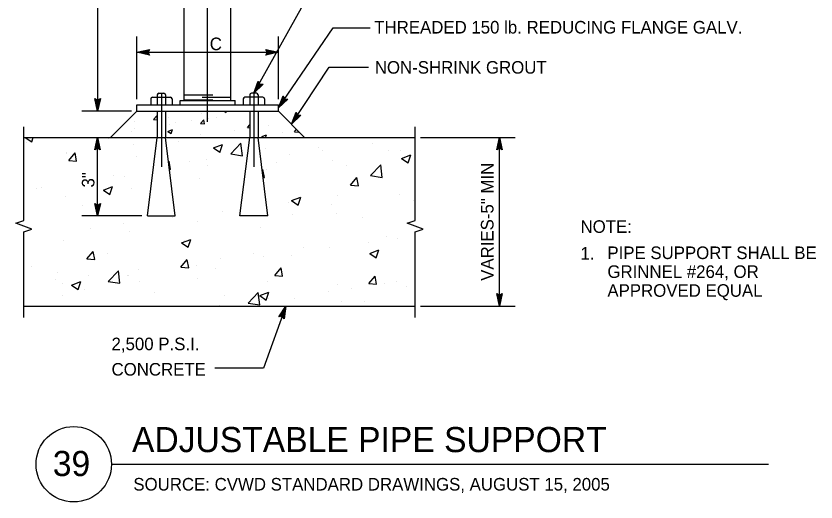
# Model space of a CAD drawing. Extents: x -121875 to -117742, y -103854 to -101122.
# Drawn here: x -121098.1 to -120716.3, y -102136.5 to -101904.5 of the extents above; entities that cross this region are included whole.
import ezdxf

# ---------------------------------------------------------------- set-up
doc = ezdxf.new("R2010")
doc.units = 0
for name, color, linetype in [('G-MARK', 7, 'Continuous'), ('G-TEXT', 7, 'Continuous'), ('Misc CnstDet(22)', 7, 'Continuous')]:
    doc.layers.add(name, color=color, linetype=linetype)

msp = doc.modelspace()

# ---------------------------------------------------------------- linework, layer by layer
at = {"layer": 'G-MARK'}
for p, q in [((-121059.15, -101866.71), (-121059.15, -101949.94)), ((-121040.4, -101944.19), (-121040.4, -101914.32)), ((-120972.82, -101944.19), (-120972.82, -101914.32)), ((-121040.4, -101921.82), (-120972.82, -101921.82)), ((-121043.02, -101949.94), (-121066.65, -101949.94)), ((-121059.15, -101999.94), (-121059.15, -101962.44)), ((-120904.96, -101962.44), (-120859.85, -101962.44)), ((-120867.35, -102042.91), (-120867.35, -101962.44)), ((-121037.94, -101999.94), (-121066.65, -101999.94)), ((-120904.96, -102042.91), (-120859.85, -102042.91))]:
    msp.add_line(p, q, dxfattribs=at)
for points in [[(-120984.54, -101941.35), (-120937.41, -101856.81), (-120928.5, -101856.81)], [(-120972.82, -101948.38), (-120946.65, -101910.1), (-120929.07, -101910.1)], [(-120966.57, -101956.19), (-120948.6, -101928.85), (-120929.85, -101928.85)], [(-120969.3, -102042.91), (-120980.01, -102072.63), (-121003.19, -102072.65)]]:
    msp.add_lwpolyline(points, dxfattribs=at)
at = {"layer": 'G-TEXT'}
for p, q in [((-121040.4, -101921.82), (-121034.4, -101920.49)), ((-121034.4, -101923.16), (-121040.4, -101921.82)), ((-121040.4, -101921.82), (-121040.4, -101921.82)), ((-121034.61, -101922.8), (-121039.02, -101921.82)), ((-121039, -101921.82), (-121034.63, -101920.85)), ((-121037.63, -101921.82), (-121034.81, -101921.19)), ((-121034.85, -101922.44), (-121037.63, -101921.82)), ((-121036.25, -101921.82), (-121035.04, -101921.55)), ((-121035.02, -101922.1), (-121036.25, -101921.82)), ((-121034.4, -101920.49), (-121035.2, -101921.82)), ((-121035.2, -101921.82), (-121034.4, -101923.16)), ((-121034.4, -101920.49), (-121034.4, -101920.49)), ((-120978.02, -101921.82), (-120978.82, -101920.48)), ((-120978.82, -101920.48), (-120978.82, -101920.48)), ((-120978.82, -101920.48), (-120972.82, -101921.82)), ((-120972.82, -101921.82), (-120978.82, -101923.15)), ((-120978.82, -101923.15), (-120978.02, -101921.82)), ((-120978.6, -101920.83), (-120974.2, -101921.82)), ((-120974.21, -101921.82), (-120978.58, -101922.79)), ((-120975.58, -101921.82), (-120978.41, -101922.44)), ((-120978.37, -101921.19), (-120975.58, -101921.82)), ((-120978.19, -101921.54), (-120976.96, -101921.82)), ((-120976.96, -101921.82), (-120978.17, -101922.08)), ((-120972.82, -101921.82), (-120972.82, -101921.82)), ((-121034.4, -101923.16), (-121034.4, -101923.16)), ((-120978.82, -101923.15), (-120978.82, -101923.15)), ((-120984.54, -101941.35), (-120982.44, -101935.57)), ((-120980.19, -101937.01), (-120984.54, -101941.35)), ((-120980.6, -101937), (-120983.8, -101940.19)), ((-120983.79, -101940.17), (-120982.26, -101935.96)), ((-120983.05, -101939.02), (-120982.06, -101936.3)), ((-120981.03, -101937), (-120983.05, -101939.02)), ((-120982.44, -101935.57), (-120982.44, -101935.57)), ((-120982.44, -101935.57), (-120981.75, -101936.96)), ((-120982.31, -101937.85), (-120981.89, -101936.69)), ((-120981.42, -101936.96), (-120982.31, -101937.85)), ((-120981.75, -101936.96), (-120980.19, -101937.01)), ((-120980.19, -101937.01), (-120980.19, -101937.01)), ((-120984.54, -101941.35), (-120984.54, -101941.35)), ((-121059.15, -101949.94), (-121060.48, -101943.94)), ((-121060.48, -101943.94), (-121060.48, -101943.94)), ((-121060.48, -101943.94), (-121059.15, -101944.74)), ((-121059.15, -101948.55), (-121060.12, -101944.18)), ((-121059.14, -101947.18), (-121059.77, -101944.36)), ((-121059.14, -101945.8), (-121059.41, -101944.59)), ((-121059.15, -101944.74), (-121057.81, -101943.94)), ((-121057.81, -101943.94), (-121059.15, -101949.94)), ((-121058.16, -101944.16), (-121059.15, -101948.56)), ((-121058.52, -101944.39), (-121059.14, -101947.18)), ((-121058.87, -101944.57), (-121059.14, -101945.8)), ((-121057.81, -101943.94), (-121057.81, -101943.94)), ((-120972.82, -101948.38), (-120970.53, -101942.68)), ((-120968.33, -101944.18), (-120972.82, -101948.38)), ((-120972.04, -101947.23), (-120970.37, -101943.07)), ((-120968.74, -101944.16), (-120972.04, -101947.24)), ((-120971.26, -101946.1), (-120970.18, -101943.42)), ((-120969.17, -101944.15), (-120971.26, -101946.1)), ((-120970.53, -101942.68), (-120970.53, -101942.68)), ((-120970.53, -101942.68), (-120969.88, -101944.09)), ((-120970.48, -101944.96), (-120970.02, -101943.81)), ((-120969.56, -101944.1), (-120970.48, -101944.96)), ((-120969.88, -101944.09), (-120968.33, -101944.18)), ((-120968.33, -101944.18), (-120968.33, -101944.18)), ((-120972.82, -101948.38), (-120972.82, -101948.38)), ((-121059.15, -101949.94), (-121059.15, -101949.94)), ((-120966.57, -101956.19), (-120964.41, -101950.44)), ((-120962.17, -101951.9), (-120966.57, -101956.19)), ((-120965.81, -101955.03), (-120964.24, -101950.83)), ((-120962.59, -101951.88), (-120965.81, -101955.04)), ((-120965.06, -101953.88), (-120964.04, -101951.17)), ((-120963.02, -101951.88), (-120965.06, -101953.88)), ((-120964.41, -101950.44), (-120964.41, -101950.44)), ((-120964.41, -101950.44), (-120963.73, -101951.84)), ((-120964.3, -101952.72), (-120963.87, -101951.56)), ((-120963.4, -101951.84), (-120964.3, -101952.72)), ((-120963.73, -101951.84), (-120962.17, -101951.9)), ((-120962.17, -101951.9), (-120962.17, -101951.9)), ((-120966.57, -101956.19), (-120966.57, -101956.19)), ((-121060.49, -101968.44), (-121059.15, -101962.44)), ((-121060.13, -101968.23), (-121059.15, -101963.82)), ((-121059.15, -101962.44), (-121059.15, -101962.44)), ((-121059.15, -101962.44), (-121057.82, -101968.44)), ((-121059.14, -101963.83), (-121058.17, -101968.21)), ((-120868.69, -101968.44), (-120867.35, -101962.44)), ((-120868.33, -101968.23), (-120867.35, -101963.82)), ((-120867.35, -101962.44), (-120867.35, -101962.44)), ((-120867.35, -101962.44), (-120866.02, -101968.44)), ((-120867.35, -101963.83), (-120866.38, -101968.21)), ((-121059.15, -101967.64), (-121060.49, -101968.44)), ((-121059.77, -101967.99), (-121059.15, -101965.21)), ((-121059.42, -101967.82), (-121059.15, -101966.59)), ((-121059.15, -101965.21), (-121058.52, -101968.03)), ((-121059.15, -101966.59), (-121058.88, -101967.8)), ((-121057.82, -101968.44), (-121059.15, -101967.64)), ((-120867.35, -101967.64), (-120868.69, -101968.44)), ((-120867.97, -101967.99), (-120867.35, -101965.21)), ((-120867.63, -101967.82), (-120867.35, -101966.59)), ((-120867.35, -101965.21), (-120866.72, -101968.03)), ((-120867.35, -101966.59), (-120867.08, -101967.8)), ((-120866.02, -101968.44), (-120867.35, -101967.64)), ((-121060.49, -101968.44), (-121060.49, -101968.44)), ((-121057.82, -101968.44), (-121057.82, -101968.44)), ((-120868.69, -101968.44), (-120868.69, -101968.44)), ((-120866.02, -101968.44), (-120866.02, -101968.44)), ((-121059.15, -101999.94), (-121060.48, -101993.94)), ((-121060.48, -101993.94), (-121060.48, -101993.94)), ((-121060.48, -101993.94), (-121059.15, -101994.74)), ((-121059.15, -101998.55), (-121060.12, -101994.18)), ((-121059.14, -101997.18), (-121059.77, -101994.36)), ((-121059.14, -101995.8), (-121059.41, -101994.59)), ((-121059.15, -101994.74), (-121057.81, -101993.94)), ((-121057.81, -101993.94), (-121059.15, -101999.94)), ((-121058.16, -101994.16), (-121059.15, -101998.56)), ((-121058.52, -101994.39), (-121059.14, -101997.18)), ((-121058.87, -101994.57), (-121059.14, -101995.8)), ((-121057.81, -101993.94), (-121057.81, -101993.94)), ((-121059.15, -101999.94), (-121059.15, -101999.94)), ((-120867.35, -102042.91), (-120868.68, -102036.91)), ((-120868.68, -102036.91), (-120868.68, -102036.91)), ((-120868.68, -102036.91), (-120867.35, -102037.71)), ((-120867.35, -102041.52), (-120868.32, -102037.15)), ((-120867.35, -102040.15), (-120867.97, -102037.32)), ((-120867.35, -102038.77), (-120867.61, -102037.56)), ((-120867.35, -102037.71), (-120866.01, -102036.91)), ((-120866.01, -102036.91), (-120867.35, -102042.91)), ((-120866.36, -102037.13), (-120867.35, -102041.53)), ((-120866.72, -102037.36), (-120867.35, -102040.15)), ((-120867.07, -102037.54), (-120867.35, -102038.77)), ((-120866.01, -102036.91), (-120866.01, -102036.91)), ((-120972.59, -102048.11), (-120969.3, -102042.91)), ((-120972.18, -102048.02), (-120969.77, -102044.21)), ((-120969.77, -102044.22), (-120970.34, -102048.67)), ((-120969.3, -102042.91), (-120970.08, -102049.01)), ((-120969.3, -102042.91), (-120969.3, -102042.91)), ((-120867.35, -102042.91), (-120867.35, -102042.91)), ((-120971.06, -102047.81), (-120972.59, -102048.11)), ((-120972.59, -102048.11), (-120972.59, -102048.11)), ((-120971.76, -102047.93), (-120970.24, -102045.51)), ((-120971.38, -102047.88), (-120970.7, -102046.81)), ((-120970.08, -102049.01), (-120971.06, -102047.81)), ((-120970.7, -102046.81), (-120970.86, -102048.04)), ((-120970.24, -102045.51), (-120970.6, -102048.38)), ((-120970.08, -102049.01), (-120970.08, -102049.01))]:
    msp.add_line(p, q, dxfattribs=at)
at = {"layer": 'Misc CnstDet(22)'}
for p, q in [((-121006.61, -101955.02), (-121006.61, -101695.26)), ((-121017.74, -101944.87), (-121017.74, -101832.76)), ((-120995.47, -101944.87), (-120995.47, -101832.76)), ((-121029.85, -101941.35), (-121027.51, -101941.35)), ((-121028.68, -101941.35), (-121028.68, -101976.51)), ((-120983.36, -101941.35), (-120985.71, -101941.35)), ((-120984.54, -101941.35), (-120984.54, -101976.51)), ((-121033.76, -101944.08), (-121033.76, -101946.82)), ((-121032.97, -101943.3), (-121024.38, -101943.3)), ((-121030.63, -101942.13), (-121030.63, -101946.82)), ((-121026.72, -101942.13), (-121026.72, -101946.82)), ((-121023.6, -101944.08), (-121023.6, -101946.82)), ((-121019.69, -101944.87), (-120993.52, -101944.87)), ((-121019.69, -101946.82), (-121019.69, -101944.87)), ((-121017.74, -101942.13), (-121004.07, -101942.13)), ((-121017.74, -101944.48), (-121004.07, -101944.48)), ((-121009.15, -101943.3), (-120995.47, -101943.3)), ((-120993.52, -101946.82), (-120993.52, -101944.87)), ((-120989.61, -101944.08), (-120989.61, -101946.82)), ((-120980.24, -101943.3), (-120988.83, -101943.3)), ((-120986.49, -101942.13), (-120986.49, -101946.82)), ((-120982.58, -101942.13), (-120982.58, -101946.82)), ((-120979.46, -101944.08), (-120979.46, -101946.82)), ((-121040.4, -101946.82), (-120972.82, -101946.82)), ((-121040.4, -101949.94), (-121040.4, -101946.82)), ((-120972.82, -101949.94), (-120972.82, -101946.82)), ((-121052.9, -101962.44), (-121040.4, -101949.94)), ((-121040.4, -101949.94), (-120972.82, -101949.94)), ((-121032.38, -101953.86), (-121030.88, -101952.07)), ((-121030.63, -101953.41), (-121030.88, -101952.07)), ((-121030.63, -101949.94), (-121030.63, -101962.44)), ((-121026.72, -101949.94), (-121026.72, -101962.44)), ((-121009.54, -101950.87), (-121009.54, -101950.87)), ((-120998.7, -101949.94), (-120997.82, -101950.54)), ((-120997.82, -101950.55), (-120997.61, -101949.94)), ((-120988.14, -101950.12), (-120988.14, -101950.12)), ((-120986.49, -101949.94), (-120986.49, -101962.44)), ((-120982.58, -101949.94), (-120982.58, -101962.44)), ((-120982.53, -101950.26), (-120982.53, -101950.26)), ((-120960.32, -101962.44), (-120972.82, -101949.94)), ((-121041.37, -101955.07), (-121041.37, -101955.07)), ((-121032.38, -101953.86), (-121030.63, -101954.02)), ((-121025.33, -101952.87), (-121025.33, -101952.87)), ((-121024.59, -101956.37), (-121024.59, -101956.37)), ((-121021.92, -101955.44), (-121021.92, -101955.44)), ((-121014.1, -101954.41), (-121014.1, -101954.41)), ((-121009.97, -101955.82), (-121008.46, -101954.03)), ((-121009.97, -101955.82), (-121008.1, -101955.99)), ((-121008.1, -101955.99), (-121008.46, -101954.03)), ((-121006.36, -101953.25), (-121006.36, -101953.25)), ((-121002.26, -101952.86), (-121002.26, -101952.86)), ((-120987.56, -101957.78), (-120986.49, -101956.51)), ((-121042.81, -101959.5), (-121042.81, -101959.5)), ((-121041.66, -101958.04), (-121041.66, -101958.04)), ((-121025.63, -101959.57), (-121023.44, -101958.73)), ((-121025.63, -101959.57), (-121024.07, -101960.62)), ((-121024.07, -101960.63), (-121023.44, -101958.74)), ((-120993.69, -101958.93), (-120993.69, -101958.93)), ((-120987.56, -101957.78), (-120986.49, -101957.88)), ((-120977.65, -101956.73), (-120977.65, -101956.73)), ((-120971.09, -101960), (-120971.09, -101960)), ((-120965.14, -101959.74), (-120964.17, -101958.59)), ((-120965.14, -101959.74), (-120963.27, -101959.91)), ((-120963.27, -101959.92), (-120963.37, -101959.39)), ((-121094.3, -101962.44), (-120907.58, -101962.44)), ((-121093.67, -101962.46), (-121093.63, -101962.44)), ((-121093.67, -101962.46), (-121090.56, -101964.56)), ((-121090.56, -101964.57), (-121089.85, -101962.44)), ((-121053.73, -101963.06), (-121053.73, -101963.06)), ((-121035.32, -101999.94), (-121030.63, -101962.44)), ((-121022.04, -101999.94), (-121026.72, -101962.44)), ((-121009.92, -101961.27), (-121009.92, -101961.27)), ((-120991.18, -101999.94), (-120986.49, -101962.44)), ((-120977.9, -101999.94), (-120982.58, -101962.44)), ((-120980.72, -101962.08), (-120978.53, -101961.24)), ((-120980.72, -101962.08), (-120980.17, -101962.44)), ((-120978.93, -101962.44), (-120978.53, -101961.24)), ((-121092.89, -101964.79), (-121092.89, -101964.79)), ((-121042.2, -101965.81), (-121042.2, -101965.81)), ((-121020.37, -101964.47), (-121020.37, -101964.47)), ((-121003.85, -101967.47), (-120999.47, -101965.79)), ((-121003.85, -101967.47), (-121000.74, -101969.56)), ((-121000.74, -101969.57), (-120999.47, -101965.79)), ((-120995.58, -101970.3), (-120990.71, -101965.23)), ((-120990.02, -101971.17), (-120990.71, -101965.24)), ((-120987, -101965.88), (-120987, -101965.88)), ((-120978.81, -101967.92), (-120978.81, -101967.92)), ((-120953.64, -101967.29), (-120953.64, -101967.29)), ((-120928.08, -101965.58), (-120928.08, -101965.58)), ((-121073.92, -101970.05), (-121073.92, -101970.05)), ((-121073.77, -101969.81), (-121073.77, -101969.81)), ((-121072.88, -101973.45), (-121069.86, -101969.85)), ((-121069.14, -101973.78), (-121069.86, -101969.86)), ((-121059.15, -101977.44), (-121059.15, -101969.94)), ((-121040.55, -101971.46), (-121040.55, -101971.46)), ((-120995.58, -101970.3), (-120990.02, -101971.17)), ((-120967.4, -101970.75), (-120967.4, -101970.75)), ((-120951.75, -101968.69), (-120951.75, -101968.69)), ((-120920.27, -101968.7), (-120920.27, -101968.7)), ((-120914.38, -101968.85), (-120914.38, -101968.85)), ((-120914.03, -101972.47), (-120909.65, -101970.79)), ((-120910.92, -101974.58), (-120909.65, -101970.8)), ((-121072.88, -101973.45), (-121069.14, -101973.77)), ((-121025.27, -101974.06), (-121025.04, -101973.78)), ((-121024.31, -101977.7), (-121025.03, -101973.78)), ((-121015.26, -101974.17), (-121015.26, -101974.17)), ((-121007.19, -101972.87), (-121007.19, -101972.87)), ((-120973.82, -101974.28), (-120973.82, -101974.28)), ((-120946.84, -101973.53), (-120946.84, -101973.53)), ((-120940.46, -101975.69), (-120940.46, -101975.69)), ((-120928.88, -101980.65), (-120924.01, -101975.57)), ((-120923.32, -101981.52), (-120924.01, -101975.58)), ((-120914.03, -101972.47), (-120910.92, -101974.57)), ((-121024.82, -101977.65), (-121024.31, -101977.69)), ((-121006.87, -101975.95), (-121006.87, -101975.95)), ((-120980.62, -101978.19), (-120980.21, -101977.7)), ((-120979.48, -101981.62), (-120980.21, -101977.71)), ((-120978.41, -101977.53), (-120978.41, -101977.53)), ((-121051.71, -101980.43), (-121051.71, -101980.43)), ((-121046.19, -101981.13), (-121046.19, -101981.13)), ((-121010.5, -101981.93), (-121010.5, -101981.93)), ((-120980.19, -101981.55), (-120979.48, -101981.62)), ((-120938.39, -101985.21), (-120935.38, -101981.62)), ((-120934.65, -101985.55), (-120935.38, -101981.63)), ((-120928.88, -101980.65), (-120923.32, -101981.51)), ((-121088.16, -101986.69), (-121088.16, -101986.69)), ((-121085.66, -101986.32), (-121085.66, -101986.32)), ((-121056.36, -101987.63), (-121051.99, -101985.95)), ((-121053.25, -101989.73), (-121051.99, -101985.95)), ((-121042.96, -101986.62), (-121042.96, -101986.62)), ((-120938.39, -101985.21), (-120934.66, -101985.54)), ((-121074.53, -101990.62), (-121074.53, -101990.62)), ((-121056.36, -101987.63), (-121053.26, -101989.72)), ((-120966.54, -101992.63), (-120962.17, -101990.95)), ((-120963.43, -101994.73), (-120962.17, -101990.96)), ((-120944.52, -101990.23), (-120944.52, -101990.23)), ((-120915.14, -101989.65), (-120915.14, -101989.65)), ((-120968.19, -101993.34), (-120968.19, -101993.34)), ((-120966.54, -101992.63), (-120963.44, -101994.73)), ((-120947.6, -101994.34), (-120947.6, -101994.34)), ((-120908.49, -101992.69), (-120908.49, -101992.69)), ((-121066.16, -101994.83), (-121066.16, -101994.83)), ((-120999.44, -101997.65), (-120999.44, -101997.65)), ((-121035.32, -101999.94), (-121022.04, -101999.94)), ((-121023.31, -102000.6), (-121023.31, -102000.6)), ((-120977.9, -101999.94), (-120991.18, -101999.94)), ((-120966.07, -101999.06), (-120966.07, -101999.06)), ((-120944.94, -101998.95), (-120944.94, -101998.95)), ((-120932.71, -102000.47), (-120932.71, -102000.47)), ((-121062.63, -102005.78), (-121062.63, -102005.78)), ((-121046.98, -102003.72), (-121046.98, -102003.72)), ((-121011.26, -102002.74), (-121011.26, -102002.74)), ((-120981.39, -102005.21), (-120981.39, -102005.21)), ((-121043.72, -102007.43), (-121043.72, -102007.43)), ((-120921.49, -102009.68), (-120921.49, -102009.68)), ((-121075.29, -102011.43), (-121075.29, -102011.43)), ((-121019.06, -102012.79), (-121014.68, -102011.11)), ((-121019.06, -102012.79), (-121015.95, -102014.89)), ((-121017.84, -102011.46), (-121017.84, -102011.46)), ((-121015.95, -102014.89), (-121014.68, -102011.12)), ((-120929.96, -102012.67), (-120929.96, -102012.67)), ((-120915.9, -102010.46), (-120915.9, -102010.46)), ((-121064.21, -102020.46), (-121061.19, -102016.87)), ((-121060.47, -102020.79), (-121061.19, -102016.87)), ((-121054.29, -102017.72), (-121054.29, -102017.72)), ((-120960.97, -102014.88), (-120960.97, -102014.88)), ((-120948.36, -102015.14), (-120948.36, -102015.14)), ((-120929.24, -102017.79), (-120924.86, -102016.11)), ((-120926.13, -102019.9), (-120924.86, -102016.12)), ((-121064.21, -102020.46), (-121060.47, -102020.78)), ((-121019.38, -102024.38), (-121016.36, -102020.79)), ((-121015.64, -102024.71), (-121016.36, -102020.8)), ((-121000.28, -102020.05), (-121000.28, -102020.05)), ((-120984.64, -102017.99), (-120984.64, -102017.99)), ((-120979.93, -102019.14), (-120979.93, -102019.14)), ((-120966.41, -102018.93), (-120966.41, -102018.93)), ((-120929.24, -102017.79), (-120926.13, -102019.89)), ((-121090.74, -102023.98), (-121090.74, -102023.98)), ((-121039.75, -102025.25), (-121039.75, -102025.25)), ((-121019.38, -102024.38), (-121015.64, -102024.71)), ((-121012.02, -102023.54), (-121012.02, -102023.54)), ((-121002.86, -102025.19), (-121002.86, -102025.19)), ((-120974.55, -102028.3), (-120971.53, -102024.71)), ((-120970.81, -102028.64), (-120971.53, -102024.72)), ((-121078.34, -102026.77), (-121078.34, -102026.77)), ((-121063.43, -102028.37), (-121063.43, -102028.37)), ((-121054, -102031.19), (-121049.13, -102026.11)), ((-121048.44, -102032.05), (-121049.13, -102026.12)), ((-121044.97, -102028.18), (-121044.97, -102028.18)), ((-121044.48, -102028.23), (-121044.48, -102028.23)), ((-120974.55, -102028.3), (-120970.81, -102028.63)), ((-120929.72, -102032.22), (-120926.71, -102028.63)), ((-120925.98, -102032.56), (-120926.71, -102028.64)), ((-121079.07, -102030.43), (-121079.07, -102030.43)), ((-121076.05, -102032.23), (-121076.05, -102032.23)), ((-121071.57, -102032.95), (-121067.2, -102031.27)), ((-121071.57, -102032.95), (-121068.46, -102035.04)), ((-121068.46, -102035.05), (-121067.19, -102031.27)), ((-121054, -102031.19), (-121048.44, -102032.05)), ((-121039.31, -102031.44), (-121039.31, -102031.44)), ((-121011.61, -102029.59), (-121011.61, -102029.59)), ((-120978.24, -102031), (-120978.24, -102031)), ((-120944.88, -102032.41), (-120944.88, -102032.41)), ((-120929.72, -102032.22), (-120925.98, -102032.55)), ((-120922.29, -102032.27), (-120922.29, -102032.27)), ((-120916.66, -102031.26), (-120916.66, -102031.26)), ((-121065.16, -102035.16), (-121065.16, -102035.16)), ((-121031.79, -102036.57), (-121031.79, -102036.57)), ((-120987.3, -102041.53), (-120982.43, -102036.46)), ((-120981.74, -102042.4), (-120982.43, -102036.46)), ((-120981.75, -102037.95), (-120977.38, -102036.27)), ((-120978.64, -102040.06), (-120977.37, -102036.28)), ((-120949.12, -102035.95), (-120949.12, -102035.95)), ((-120937.94, -102034.33), (-120937.94, -102034.33)), ((-120911.52, -102033.82), (-120911.52, -102033.82)), ((-121075.76, -102037.7), (-121075.76, -102037.7)), ((-120998.43, -102037.98), (-120998.43, -102037.98)), ((-120981.75, -102037.95), (-120978.64, -102040.05)), ((-120980.69, -102039.95), (-120980.69, -102039.95)), ((-120977.41, -102039.53), (-120977.41, -102039.53)), ((-120965.07, -102039.39), (-120965.07, -102039.39)), ((-121094.3, -102042.91), (-120907.58, -102042.91)), ((-121001.08, -102042.64), (-121001.08, -102042.64)), ((-120987.3, -102041.53), (-120981.74, -102042.39)), ((-120942.54, -102040.8), (-120942.54, -102040.8)), ((-120931.7, -102040.8), (-120931.7, -102040.8)), ((-121052.51, -102118.45), (-120739.05, -102118.45))]:
    msp.add_line(p, q, dxfattribs=at)
for points in [[(-121094.3, -102048.38), (-121094.3, -102007.54), (-121090.55, -102006.17), (-121098.06, -102003.44), (-121094.3, -102002.07), (-121094.3, -101957.37)], [(-120907.58, -102048.38), (-120907.58, -102007.54), (-120903.83, -102006.17), (-120911.34, -102003.44), (-120907.58, -102002.07), (-120907.58, -101957.37)]]:
    msp.add_lwpolyline(points, dxfattribs=at)
msp.add_circle((-121070.51, -102118.45), 18, dxfattribs=at)
for centre, start, end in [((-121029.85, -101942.13), 90, 180), ((-121027.51, -101942.13), 0, 90), ((-120985.71, -101942.13), 90, 180), ((-120983.36, -101942.13), 0, 90), ((-121032.97, -101944.08), 90, 180), ((-121024.38, -101944.08), 0, 90), ((-120988.83, -101944.08), 90, 180), ((-120980.24, -101944.08), 0, 90)]:
    msp.add_arc(centre, 0.781, start, end, dxfattribs=at)

# ---------------------------------------------------------------- texts
for s, height, p in [('THREADED 150 lb. REDUCING FLANGE GALV.', 6, (-120927.11, -101912.86)), ('C', 6, (-121005.6, -101920.8)), ('NON-SHRINK GROUT', 6, (-120926.84, -101932.02)), ('NOTE:', 6, (-120828.68, -102008)), ('1.', 6, (-120828.68, -102020.77)), ('PIPE SUPPORT SHALL BE', 6, (-120815.85, -102020.51)), ('GRINNEL #264, OR', 6, (-120815.85, -102029.51)), ('APPROVED EQUAL', 6, (-120815.85, -102038.51)), ('2,500 P.S.I.', 6, (-121052.47, -102064.01)), ('CONCRETE', 6, (-121052.47, -102076.12)), ('ADJUSTABLE PIPE SUPPORT', 12, (-121042.71, -102112.66)), ('39', 12, (-121080.5, -102124.07)), ('SOURCE: CVWD STANDARD DRAWINGS, AUGUST 15, 2005', 6, (-121042.06, -102130.98))]:
    msp.add_text(s, height=height, dxfattribs=at).set_placement(p)
for s, p in [('VARIES-5" MIN', (-120870.2, -102030.89)), ('3"', (-121060.64, -101986.35))]:
    msp.add_text(s, height=6, rotation=90, dxfattribs=at).set_placement(p)

doc.saveas('drawing.dxf')
